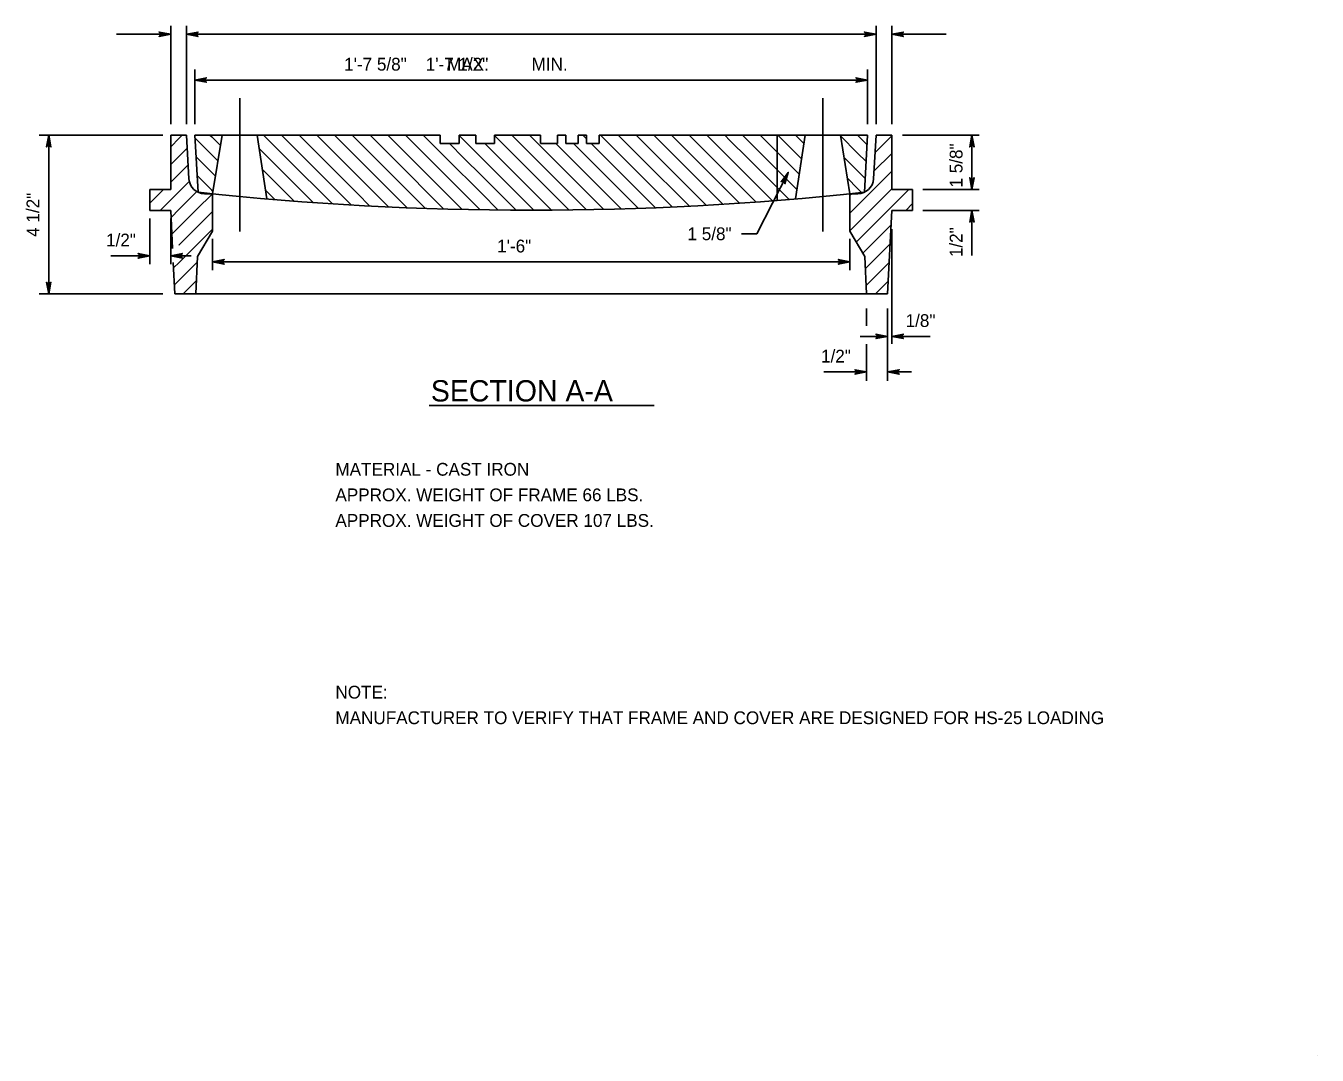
# Model space of a CAD drawing. Extents: x 2.36 to 8.41, y -8.97 to 0.21.
# Drawn here: x 2.36 to 8.41, y -8.97 to -4.14 of the extents above; entities that cross this region are included whole.
import ezdxf

# ---------------------------------------------------------------- set-up
doc = ezdxf.new("R2010")
doc.units = 0
for name, color, linetype in [('DETL-DIMS', 7, 'Continuous'), ('DETL-LINE', 7, 'Continuous'), ('DETL-NOTE', 7, 'Continuous'), ('DETL-PATT', 7, 'Continuous'), ('DETL-TITL', 7, 'Continuous'), ('TTLB-TEXT', 7, 'Continuous')]:
    doc.layers.add(name, color=color, linetype=linetype)

msp = doc.modelspace()

# ---------------------------------------------------------------- linework, layer by layer
at = {"layer": 'DETL-DIMS'}
for p, q in [((2.7818, -4.1759), (3.0367, -4.1759)), ((3.0367, -4.5989), (3.0367, -4.1367)), ((3.1102, -4.5989), (3.1102, -4.1367)), ((3.1102, -4.1759), (6.3455, -4.1759)), ((6.3455, -4.5989), (6.3455, -4.1367)), ((6.419, -4.5989), (6.419, -4.1367)), ((6.419, -4.1759), (6.6739, -4.1759)), ((3.1495, -4.5989), (3.1495, -4.3416)), ((6.3062, -4.5989), (6.3062, -4.3416)), ((3.1495, -4.391), (6.3062, -4.391)), ((3.3602, -5.1024), (3.3602, -4.4764)), ((6.0955, -5.1024), (6.0955, -4.4764)), ((2.9998, -4.6499), (2.4194, -4.6499)), ((2.4643, -4.6499), (2.4643, -5.395)), ((6.4696, -4.6499), (6.829, -4.6499)), ((6.7953, -4.6499), (6.7953, -4.9048)), ((5.9339, -4.8242), (5.7867, -5.1125)), ((6.5649, -4.9048), (6.829, -4.9048)), ((6.5649, -5.0028), (6.829, -5.0028)), ((6.7953, -5.0028), (6.7953, -5.2141)), ((2.9386, -5.041), (2.9386, -5.2547)), ((3.0367, -5.041), (3.0367, -5.2547)), ((3.2327, -5.1357), (3.2327, -5.2827)), ((5.7867, -5.1125), (5.7141, -5.1125)), ((6.2229, -5.1357), (6.2229, -5.2827)), ((6.419, -5.0911), (6.419, -5.6296)), ((2.7551, -5.216), (2.9386, -5.216)), ((3.0367, -5.216), (3.1334, -5.216)), ((3.2327, -5.2441), (6.2229, -5.2441)), ((2.9998, -5.395), (2.4194, -5.395)), ((6.3014, -5.4627), (6.3014, -5.5439)), ((6.3994, -5.4627), (6.3994, -5.8025)), ((6.3994, -5.5939), (6.2715, -5.5939)), ((6.3014, -5.6305), (6.3014, -5.8025)), ((6.6001, -5.5939), (6.419, -5.5939)), ((6.3014, -5.7608), (6.1007, -5.7608)), ((6.5113, -5.7608), (6.3994, -5.7608))]:
    msp.add_line(p, q, dxfattribs=at)
for points in [[(3.0367, -4.1759), (2.9818, -4.1862), (2.9861, -4.1833), (2.9882, -4.1796), (2.9889, -4.1759), (2.9882, -4.1723), (2.9861, -4.1686), (2.9818, -4.1657), (3.0367, -4.1759), (2.9861, -4.1686), (2.9882, -4.1723), (3.0367, -4.1759), (2.9889, -4.1759), (2.9882, -4.1796), (3.0367, -4.1759), (2.9861, -4.1833)], [(3.1102, -4.1759), (3.165, -4.1657), (3.1608, -4.1686), (3.1586, -4.1723), (3.158, -4.1759), (3.1586, -4.1796), (3.1608, -4.1833), (3.165, -4.1862), (3.1102, -4.1759), (3.1608, -4.1833), (3.1586, -4.1796), (3.1102, -4.1759), (3.158, -4.1759), (3.1586, -4.1723), (3.1102, -4.1759), (3.1608, -4.1686)], [(6.3455, -4.1759), (6.2907, -4.1862), (6.2949, -4.1833), (6.2971, -4.1796), (6.2977, -4.1759), (6.2971, -4.1723), (6.2949, -4.1686), (6.2907, -4.1657), (6.3455, -4.1759), (6.2949, -4.1686), (6.2971, -4.1723), (6.3455, -4.1759), (6.2977, -4.1759), (6.2971, -4.1796), (6.3455, -4.1759), (6.2949, -4.1833)], [(6.419, -4.1759), (6.4738, -4.1657), (6.4696, -4.1686), (6.4674, -4.1723), (6.4668, -4.1759), (6.4674, -4.1796), (6.4696, -4.1833), (6.4738, -4.1862), (6.419, -4.1759), (6.4696, -4.1833), (6.4674, -4.1796), (6.419, -4.1759), (6.4668, -4.1759), (6.4674, -4.1723), (6.419, -4.1759), (6.4696, -4.1686)], [(3.1495, -4.391), (3.2043, -4.3807), (3.2001, -4.3836), (3.1979, -4.3873), (3.1973, -4.391), (3.1979, -4.3946), (3.2001, -4.3983), (3.2043, -4.4012), (3.1495, -4.391), (3.2001, -4.3983), (3.1979, -4.3946), (3.1495, -4.391), (3.1973, -4.391), (3.1979, -4.3873), (3.1495, -4.391), (3.2001, -4.3836)], [(6.3062, -4.391), (6.2514, -4.4012), (6.2556, -4.3983), (6.2578, -4.3946), (6.2584, -4.391), (6.2578, -4.3873), (6.2556, -4.3836), (6.2514, -4.3807), (6.3062, -4.391), (6.2556, -4.3836), (6.2578, -4.3873), (6.3062, -4.391), (6.2584, -4.391), (6.2578, -4.3946), (6.3062, -4.391), (6.2556, -4.3983)], [(2.4643, -4.6499), (2.4746, -4.7047), (2.4717, -4.7005), (2.468, -4.6983), (2.4643, -4.6976), (2.4606, -4.6983), (2.4569, -4.7005), (2.454, -4.7047), (2.4643, -4.6499), (2.4569, -4.7005), (2.4606, -4.6983), (2.4643, -4.6499), (2.4643, -4.6976), (2.468, -4.6983), (2.4643, -4.6499), (2.4717, -4.7005)], [(6.7953, -4.6499), (6.8056, -4.7047), (6.8026, -4.7005), (6.799, -4.6983), (6.7953, -4.6976), (6.7916, -4.6983), (6.7879, -4.7005), (6.785, -4.7047), (6.7953, -4.6499), (6.7879, -4.7005), (6.7916, -4.6983), (6.7953, -4.6499), (6.7953, -4.6976), (6.799, -4.6983), (6.7953, -4.6499), (6.8026, -4.7005)], [(5.9339, -4.8242), (5.9181, -4.8777), (5.9174, -4.8726), (5.9151, -4.869), (5.9121, -4.8667), (5.9086, -4.8656), (5.9043, -4.8659), (5.8998, -4.8683), (5.9339, -4.8242), (5.9043, -4.8659), (5.9086, -4.8656), (5.9339, -4.8242), (5.9121, -4.8667), (5.9151, -4.869), (5.9339, -4.8242), (5.9174, -4.8726)], [(6.7953, -4.9048), (6.785, -4.8499), (6.7879, -4.8542), (6.7916, -4.8563), (6.7953, -4.857), (6.799, -4.8563), (6.8026, -4.8542), (6.8056, -4.8499), (6.7953, -4.9048), (6.8026, -4.8542), (6.799, -4.8563), (6.7953, -4.9048), (6.7953, -4.857), (6.7916, -4.8563), (6.7953, -4.9048), (6.7879, -4.8542)], [(6.7953, -5.0028), (6.8056, -5.0576), (6.8026, -5.0534), (6.799, -5.0512), (6.7953, -5.0506), (6.7916, -5.0512), (6.7879, -5.0534), (6.785, -5.0576), (6.7953, -5.0028), (6.7879, -5.0534), (6.7916, -5.0512), (6.7953, -5.0028), (6.7953, -5.0506), (6.799, -5.0512), (6.7953, -5.0028), (6.8026, -5.0534)], [(2.9386, -5.216), (2.8838, -5.2262), (2.888, -5.2233), (2.8902, -5.2196), (2.8908, -5.216), (2.8902, -5.2123), (2.888, -5.2086), (2.8838, -5.2057), (2.9386, -5.216), (2.888, -5.2086), (2.8902, -5.2123), (2.9386, -5.216), (2.8908, -5.216), (2.8902, -5.2196), (2.9386, -5.216), (2.888, -5.2233)], [(3.0367, -5.216), (3.0915, -5.2057), (3.0873, -5.2086), (3.0851, -5.2123), (3.0845, -5.216), (3.0851, -5.2196), (3.0873, -5.2233), (3.0915, -5.2262), (3.0367, -5.216), (3.0873, -5.2233), (3.0851, -5.2196), (3.0367, -5.216), (3.0845, -5.216), (3.0851, -5.2123), (3.0367, -5.216), (3.0873, -5.2086)], [(3.2327, -5.2441), (3.2876, -5.2338), (3.2833, -5.2368), (3.2812, -5.2404), (3.2805, -5.2441), (3.2812, -5.2478), (3.2833, -5.2515), (3.2876, -5.2544), (3.2327, -5.2441), (3.2833, -5.2515), (3.2812, -5.2478), (3.2327, -5.2441), (3.2805, -5.2441), (3.2812, -5.2404), (3.2327, -5.2441), (3.2833, -5.2368)], [(6.2229, -5.2441), (6.1681, -5.2544), (6.1723, -5.2515), (6.1745, -5.2478), (6.1751, -5.2441), (6.1745, -5.2404), (6.1723, -5.2368), (6.1681, -5.2338), (6.2229, -5.2441), (6.1723, -5.2368), (6.1745, -5.2404), (6.2229, -5.2441), (6.1751, -5.2441), (6.1745, -5.2478), (6.2229, -5.2441), (6.1723, -5.2515)], [(2.4643, -5.395), (2.454, -5.3401), (2.4569, -5.3443), (2.4606, -5.3465), (2.4643, -5.3472), (2.468, -5.3465), (2.4717, -5.3443), (2.4746, -5.3401), (2.4643, -5.395), (2.4717, -5.3443), (2.468, -5.3465), (2.4643, -5.395), (2.4643, -5.3472), (2.4606, -5.3465), (2.4643, -5.395), (2.4569, -5.3443)], [(6.3994, -5.5939), (6.3446, -5.6041), (6.3488, -5.6012), (6.351, -5.5975), (6.3516, -5.5939), (6.351, -5.5902), (6.3488, -5.5865), (6.3446, -5.5836), (6.3994, -5.5939), (6.3488, -5.5865), (6.351, -5.5902), (6.3994, -5.5939), (6.3516, -5.5939), (6.351, -5.5975), (6.3994, -5.5939), (6.3488, -5.6012)], [(6.419, -5.5939), (6.4738, -5.5836), (6.4696, -5.5865), (6.4674, -5.5902), (6.4668, -5.5939), (6.4674, -5.5975), (6.4696, -5.6012), (6.4738, -5.6041), (6.419, -5.5939), (6.4696, -5.6012), (6.4674, -5.5975), (6.419, -5.5939), (6.4668, -5.5939), (6.4674, -5.5902), (6.419, -5.5939), (6.4696, -5.5865)], [(6.3014, -5.7608), (6.2465, -5.771), (6.2508, -5.7681), (6.2529, -5.7644), (6.2536, -5.7608), (6.2529, -5.7571), (6.2508, -5.7534), (6.2465, -5.7505), (6.3014, -5.7608), (6.2508, -5.7534), (6.2529, -5.7571), (6.3014, -5.7608), (6.2536, -5.7608), (6.2529, -5.7644), (6.3014, -5.7608), (6.2508, -5.7681)], [(6.3994, -5.7608), (6.4542, -5.7505), (6.45, -5.7534), (6.4478, -5.7571), (6.4472, -5.7608), (6.4478, -5.7644), (6.45, -5.7681), (6.4542, -5.771), (6.3994, -5.7608), (6.45, -5.7681), (6.4478, -5.7644), (6.3994, -5.7608), (6.4472, -5.7608), (6.4478, -5.7571), (6.3994, -5.7608), (6.45, -5.7534)]]:
    msp.add_lwpolyline(points, dxfattribs=at)
at = {"layer": 'DETL-LINE'}
for p, q in [((3.0367, -4.6499), (3.0367, -4.9048)), ((3.0367, -4.6499), (3.1102, -4.6499)), ((3.1102, -4.6499), (3.122, -4.8551)), ((3.1495, -4.6499), (3.1649, -4.9177)), ((3.1495, -4.6499), (3.2777, -4.6499)), ((3.2777, -4.6499), (3.233, -4.9249)), ((3.2777, -4.6499), (3.4428, -4.6499)), ((3.4428, -4.6499), (3.4873, -4.949)), ((3.4428, -4.6499), (4.3014, -4.6499)), ((4.3014, -4.6499), (4.3014, -4.6891)), ((4.3896, -4.6499), (4.3896, -4.6891)), ((4.3896, -4.6499), (4.468, -4.6499)), ((4.468, -4.6499), (4.468, -4.6891)), ((4.5563, -4.6499), (4.5563, -4.6891)), ((4.5563, -4.6499), (4.772, -4.6499)), ((4.772, -4.6499), (4.772, -4.6891)), ((4.8504, -4.6499), (4.8504, -4.6891)), ((4.8504, -4.6499), (4.8896, -4.6499)), ((4.8896, -4.6525), (4.8869, -4.6499)), ((4.8896, -4.6499), (4.8896, -4.6891)), ((4.9484, -4.6499), (4.9484, -4.6891)), ((4.9484, -4.6499), (4.9876, -4.6499)), ((4.9876, -4.6499), (4.9876, -4.6891)), ((5.0465, -4.6499), (5.0465, -4.6891)), ((5.0465, -4.6499), (6.0129, -4.6499)), ((5.882, -4.6499), (5.882, -4.9561)), ((5.9683, -4.949), (6.0129, -4.6499)), ((6.0129, -4.6499), (6.178, -4.6499)), ((6.178, -4.6499), (6.2227, -4.9249)), ((6.178, -4.6499), (6.3062, -4.6499)), ((6.3062, -4.6499), (6.2908, -4.9177)), ((6.3455, -4.6499), (6.3337, -4.8551)), ((6.3455, -4.6499), (6.419, -4.6499)), ((6.419, -4.6499), (6.419, -4.9048)), ((4.3014, -4.6891), (4.3896, -4.6891)), ((4.468, -4.6891), (4.5563, -4.6891)), ((4.772, -4.6891), (4.8504, -4.6891)), ((4.8896, -4.6891), (4.9484, -4.6891)), ((4.9876, -4.6891), (5.0465, -4.6891)), ((2.9386, -4.9048), (3.0367, -4.9048)), ((2.9386, -4.9048), (2.9386, -5.0028)), ((6.5171, -4.9048), (6.419, -4.9048)), ((6.5171, -4.9048), (6.5171, -5.0028)), ((3.1954, -4.9244), (3.2327, -4.9263)), ((3.2327, -4.9263), (3.2327, -5.1008)), ((6.2602, -4.9244), (6.2229, -4.9263)), ((6.2229, -4.9263), (6.2229, -5.1008)), ((2.9386, -5.0028), (3.0367, -5.0028)), ((3.0367, -5.0028), (3.0456, -5.1819)), ((6.419, -5.0028), (6.3994, -5.395)), ((6.5171, -5.0028), (6.419, -5.0028)), ((3.2327, -5.1008), (3.1631, -5.2185)), ((6.2229, -5.1008), (6.2925, -5.2185)), ((3.0489, -5.2474), (3.0563, -5.395)), ((3.1631, -5.2185), (3.1543, -5.395)), ((6.2925, -5.2185), (6.3014, -5.395)), ((3.0563, -5.395), (3.1543, -5.395)), ((3.1543, -5.395), (6.3994, -5.395)), ((6.3994, -5.395), (6.3014, -5.395))]:
    msp.add_line(p, q, dxfattribs=at)
for centre, radius, start, end in [((3.1954, -4.8508), 0.0735, 183.3014, 270), ((6.2602, -4.8508), 0.0735, 270, 356.6986), ((4.7278, 9.5298), 14.5319, 263.82586, 276.17413)]:
    msp.add_arc(centre, radius, start, end, dxfattribs=at)
at = {"layer": 'DETL-PATT'}
for p, q in [((3.0367, -4.7041), (3.0764, -4.6644)), ((3.0764, -4.6644), (3.0909, -4.6499)), ((3.2292, -4.7413), (3.1502, -4.6623)), ((3.2292, -4.6581), (3.2209, -4.6499)), ((3.2697, -4.6987), (3.2292, -4.6581)), ((3.5805, -4.7576), (3.4727, -4.6499)), ((3.6637, -4.7576), (3.5559, -4.6499)), ((3.7469, -4.7576), (3.6391, -4.6499)), ((3.8301, -4.7576), (3.7223, -4.6499)), ((3.9132, -4.7576), (3.8055, -4.6499)), ((3.9132, -4.6744), (3.8886, -4.6499)), ((4.0796, -4.7576), (3.9718, -4.6499)), ((4.1628, -4.7576), (4.055, -4.6499)), ((4.246, -4.7576), (4.1382, -4.6499)), ((4.3292, -4.7576), (4.2214, -4.6499)), ((4.4956, -4.7576), (4.3896, -4.6517)), ((4.6619, -4.7576), (4.5563, -4.652)), ((4.7451, -4.7576), (4.6373, -4.6499)), ((4.8283, -4.7576), (4.7205, -4.6499)), ((4.9876, -4.6674), (4.9701, -4.6499)), ((5.0779, -4.6744), (5.0533, -4.6499)), ((5.2443, -4.7576), (5.1365, -4.6499)), ((5.3275, -4.7576), (5.2197, -4.6499)), ((5.4106, -4.7576), (5.3029, -4.6499)), ((5.4938, -4.7576), (5.3861, -4.6499)), ((5.577, -4.7576), (5.4692, -4.6499)), ((5.6602, -4.7576), (5.5524, -4.6499)), ((5.6602, -4.6744), (5.6356, -4.6499)), ((5.8266, -4.7576), (5.7188, -4.6499)), ((5.9098, -4.7576), (5.802, -4.6499)), ((5.993, -4.7576), (5.8852, -4.6499)), ((6.0071, -4.6886), (5.9684, -4.6499)), ((6.2587, -4.7336), (6.1786, -4.6535)), ((6.2587, -4.6504), (6.2581, -4.6499)), ((6.3036, -4.6953), (6.2587, -4.6504)), ((6.3408, -4.7309), (6.419, -4.6527)), ((3.0764, -4.7476), (3.1137, -4.7103)), ((3.4973, -4.7576), (3.4521, -4.7125)), ((3.9964, -4.7576), (3.9132, -4.6744)), ((4.4124, -4.7576), (4.3438, -4.6891)), ((4.5788, -4.7576), (4.5102, -4.6891)), ((4.9115, -4.7576), (4.8429, -4.6891)), ((4.9947, -4.7576), (4.9261, -4.6891)), ((5.0779, -4.7576), (5.0093, -4.6891)), ((5.1611, -4.7576), (5.0779, -4.6744)), ((5.7434, -4.7576), (5.6602, -4.6744)), ((3.0367, -4.7873), (3.0764, -4.7476)), ((3.2292, -4.8245), (3.1553, -4.7506)), ((3.2581, -4.7702), (3.2292, -4.7413)), ((3.7057, -4.966), (3.4973, -4.7576)), ((3.7949, -4.972), (3.5805, -4.7576)), ((3.8835, -4.9774), (3.6637, -4.7576)), ((3.9132, -4.924), (3.7469, -4.7576)), ((3.9132, -4.8408), (3.8301, -4.7576)), ((4.1459, -4.9903), (3.9132, -4.7576)), ((4.2324, -4.9936), (3.9964, -4.7576)), ((4.3182, -4.9962), (4.0796, -4.7576)), ((4.4036, -4.9984), (4.1628, -4.7576)), ((4.4884, -5), (4.246, -4.7576)), ((4.4956, -4.924), (4.3292, -4.7576)), ((4.4956, -4.8408), (4.4124, -4.7576)), ((4.7384, -5.0005), (4.4956, -4.7576)), ((4.8228, -5.0017), (4.5788, -4.7576)), ((4.9052, -5.0009), (4.6619, -4.7576)), ((4.9872, -4.9997), (4.7451, -4.7576)), ((5.0687, -4.998), (4.8283, -4.7576)), ((5.0779, -4.924), (4.9115, -4.7576)), ((5.0779, -4.8408), (4.9947, -4.7576)), ((5.3105, -4.9902), (5.0779, -4.7576)), ((5.3903, -4.9869), (5.1611, -4.7576)), ((5.4697, -4.9831), (5.2443, -4.7576)), ((5.5486, -4.9788), (5.3275, -4.7576)), ((5.6271, -4.9741), (5.4106, -4.7576)), ((5.6602, -4.924), (5.4938, -4.7576)), ((5.6602, -4.8408), (5.577, -4.7576)), ((5.8604, -4.9578), (5.6602, -4.7576)), ((5.9373, -4.9515), (5.7434, -4.7576)), ((5.9748, -4.9058), (5.8266, -4.7576)), ((5.9856, -4.8334), (5.9098, -4.7576)), ((5.9963, -4.761), (5.993, -4.7576)), ((6.2587, -4.8168), (6.1948, -4.7528)), ((6.299, -4.7739), (6.2587, -4.7336)), ((6.3357, -4.8192), (6.419, -4.7359)), ((3.0367, -4.8705), (3.0764, -4.8308)), ((3.0764, -4.8308), (3.1182, -4.7889)), ((3.2292, -4.9077), (3.1604, -4.8389)), ((3.2465, -4.8418), (3.2292, -4.8245)), ((3.6159, -4.9594), (3.4667, -4.8102)), ((4.059, -4.9866), (3.9132, -4.8408)), ((4.6566, -5.0018), (4.4956, -4.8408)), ((5.2304, -4.9933), (5.0779, -4.8408)), ((5.783, -4.9636), (5.6602, -4.8408)), ((6.2229, -5.0152), (6.419, -4.8191)), ((6.2945, -4.8526), (6.2587, -4.8168)), ((2.9386, -4.9685), (3.0024, -4.9048)), ((3.0764, -4.914), (3.1245, -4.8659)), ((6.2587, -4.9), (6.2109, -4.8522)), ((6.2317, -5.0896), (6.419, -4.9023)), ((6.2778, -4.9191), (6.2587, -4.9)), ((6.4812, -4.9233), (6.4997, -4.9048)), ((2.9932, -4.9972), (3.0764, -4.914)), ((3.0764, -4.9972), (3.1593, -4.9142)), ((3.1596, -4.9972), (3.2308, -4.9259)), ((3.2348, -4.9133), (3.2292, -4.9077)), ((3.5255, -4.9522), (3.4812, -4.908)), ((3.9715, -4.9823), (3.9132, -4.924)), ((4.5727, -5.0012), (4.4956, -4.924)), ((5.1497, -4.9958), (5.0779, -4.924)), ((5.7053, -4.9691), (5.6602, -4.924)), ((6.2229, -4.932), (6.2298, -4.9251)), ((6.3149, -5.0896), (6.4812, -4.9233)), ((2.9876, -5.0028), (2.9932, -4.9972)), ((3.0383, -5.0353), (3.0764, -4.9972)), ((3.0764, -5.0804), (3.1596, -4.9972)), ((3.0764, -5.1636), (3.2327, -5.0072)), ((6.4849, -5.0028), (6.5171, -4.9706)), ((3.0423, -5.1145), (3.0764, -5.0804)), ((6.398, -5.0896), (6.4156, -5.0721)), ((3.0764, -5.2467), (3.2327, -5.0904)), ((6.2229, -5.0984), (6.2317, -5.0896)), ((6.2529, -5.1515), (6.3149, -5.0896)), ((6.2839, -5.2038), (6.398, -5.0896)), ((3.0749, -5.165), (3.0764, -5.1636)), ((6.2954, -5.2755), (6.4112, -5.1597)), ((3.0502, -5.2729), (3.0764, -5.2467)), ((3.0764, -5.3299), (3.1618, -5.2445)), ((6.2994, -5.3547), (6.4068, -5.2473)), ((3.0541, -5.3522), (3.0764, -5.3299)), ((3.0945, -5.395), (3.1575, -5.332)), ((6.3423, -5.395), (6.4024, -5.3348))]:
    msp.add_line(p, q, dxfattribs=at)
at = {"layer": 'DETL-TITL'}
msp.add_line((4.249, -5.9179), (5.3047, -5.9179), dxfattribs=at)
at = {"layer": 'TTLB-TEXT'}
msp.add_line((8.4149, -8.9665), (8.4149, -8.9665), dxfattribs=at)

# ---------------------------------------------------------------- texts
at = {"layer": 'DETL-NOTE'}
for s, p in [('1\'-7 5/8"    1\'-7 1/2"', (3.8503, -4.3468)), ('MAX.         MIN.', (4.3329, -4.3468)), ('1 5/8"', (5.461, -5.1425)), ('1/2"', (2.7333, -5.1718)), ('1\'-6"', (4.5682, -5.2)), ('1/8"', (6.4842, -5.5497)), ('1/2"', (6.0874, -5.7166)), ('MATERIAL - CAST IRON', (3.8093, -6.2475)), ('APPROX. WEIGHT OF FRAME 66 LBS.', (3.8093, -6.3675)), ('APPROX. WEIGHT OF COVER 107 LBS.', (3.8093, -6.4875)), ('NOTE:', (3.8093, -7.2933)), ('MANUFACTURER TO VERIFY THAT FRAME AND COVER ARE DESIGNED FOR HS-25 LOADING', (3.8093, -7.4133))]:
    msp.add_text(s, height=0.06, dxfattribs=at).set_placement(p)
for s, p in [('1 5/8"', (6.7512, -4.8953)), ('4 1/2"', (2.4202, -5.1269)), ('1/2"', (6.7512, -5.222))]:
    msp.add_text(s, height=0.06, rotation=90, dxfattribs=at).set_placement(p)
at = {"layer": 'DETL-TITL'}
msp.add_text('SECTION A-A', height=0.1, dxfattribs=at).set_placement((4.2569, -5.8993))

doc.saveas('drawing.dxf')
